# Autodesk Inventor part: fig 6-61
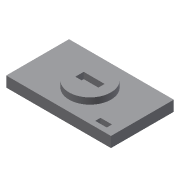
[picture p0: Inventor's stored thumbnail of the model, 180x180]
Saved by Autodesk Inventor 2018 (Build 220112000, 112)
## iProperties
Created: 2007-01
Part Number: fig 6-61
Document SubType Name: Modeling
Designer: Administrator
Density: 1 g/cm^3
Material: Generic
Appearance: Default
Author: Administrator
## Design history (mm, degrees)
sketch "Sketch1"
  geometry: L1 (-50, 30)-(50, 30); L2 (50, 30)-(50, -30); L3 (50, -30)-(-50, -30); L4 (-50, -30)-(-50, 30); 1 further point
  constraints: 8 end point, 2 parallel, 1 horizontal, 1 perpendicular, 1 other
  dimensions: "d0" = 50 distance from line of L4 point (0, 0); "d1" = 100 distance of L1.start L1.end; "d2" = 30 distance from line of L3 point (0, 0); "d3" = 60 distance between parallel lines of L3 L1
extrude "Extrusion1" new body sketch "Sketch1" distance "d4" = 10; taper "d5" = 0 deg
sketch "Sketch2"
  geometry: L1 (10, -4)-(-10, -4); L2 (-10, -4)-(-10, 4); L3 (-10, 4)-(10, 4); L4 (10, 4)-(10, -4); C1 r 20 at (0, 0); 1 further point
  constraints: 8 end point, 2 parallel, 1 centre point, 1 coincident, 1 horizontal, 1 perpendicular, 1 other
  dimensions: "d6" = 40 diameter of C1; "d7" = 4 distance from line of L3 point (0, 0); "d8" = 8 distance between parallel lines of L1 L3; "d9" = 10 distance from line of L2 point (0, 0); "d10" = 20 distance between parallel lines of L4 L2
extrude "Extrusion2" join sketch "Sketch2" distance "d11" = 6; taper "d12" = 0 deg
sketch "Sketch3"
  geometry: L1 (30, -20)-(41, -20); L2 (41, -20)-(41, -25); L3 (41, -25)-(30, -25); L4 (30, -25)-(30, -20)
  constraints: 8 end point, 2 parallel, 1 horizontal, 1 perpendicular
extrude "Extrusion3" cut sketch "Sketch3" extent not by distance; stored distance "d13" = 10; taper "d14" = 0 deg
body "Solid1"
